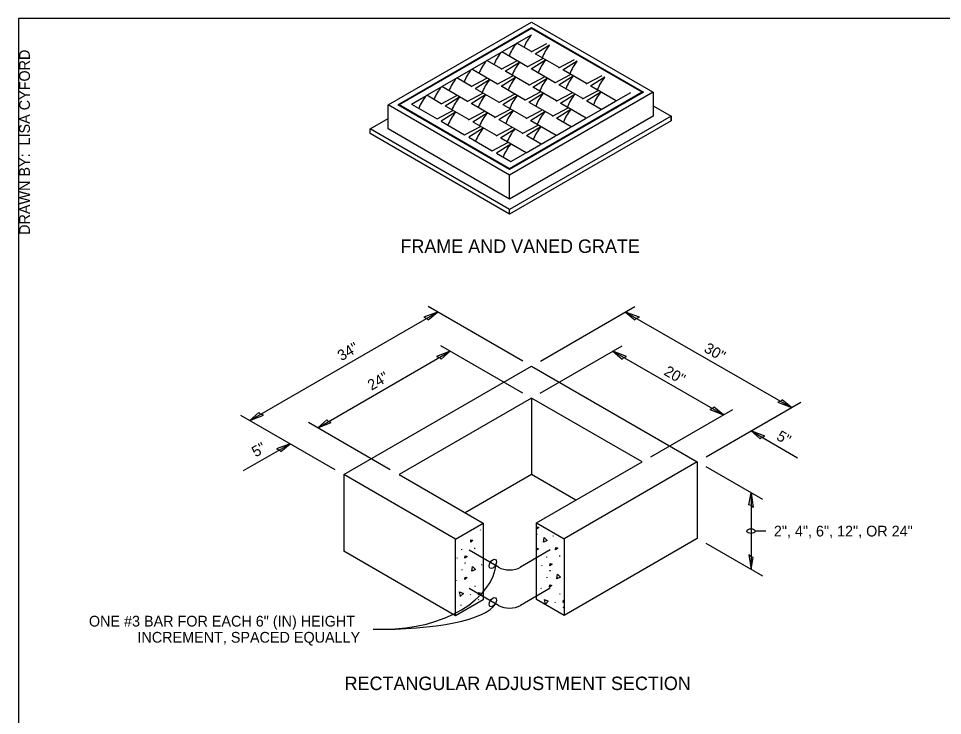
# Model space of a CAD drawing. Extents: x 99862 to 103151, y 100000 to 102076.
# Drawn here: x 99862 to 101238, y 101038 to 102076 of the extents above; entities that cross this region are included whole.
import ezdxf

# ---------------------------------------------------------------- set-up
doc = ezdxf.new("R2010")
doc.units = 0
for name, color, linetype in [('Level 1', 7, 'Continuous'), ('Level 11', 7, 'Continuous'), ('Level 12', 7, 'Continuous'), ('Level 13', 7, 'Continuous'), ('Level 15', 7, 'Continuous'), ('Level 17', 7, 'Continuous'), ('Level 20', 7, 'Continuous'), ('Level 3', 7, 'Continuous'), ('Level 44', 7, 'Continuous'), ('Level 62', 7, 'Continuous'), ('Level 8', 7, 'Continuous'), ('Level 9', 7, 'Continuous')]:
    doc.layers.add(name, color=color, linetype=linetype)

msp = doc.modelspace()

# ---------------------------------------------------------------- linework, layer by layer
at = {"layer": 'Level 1'}
msp.add_lwpolyline([(99862, 99999.5), (103151, 99999.5), (103151, 102075.5), (99862, 102075.5)], close=True, dxfattribs=at)
at = {"layer": 'Level 11'}
for p, q in [((100346.6, 101396.2), (100626.3, 101557.6)), ((100626.3, 101557.6), (100873, 101415.2)), ((100626.3, 101510.1), (100428.8, 101396.2)), ((100626.3, 101510.1), (100626.3, 101453.1)), ((100790.8, 101415.2), (100626.3, 101510.1)), ((100626.3, 101453.1), (100626.3, 101396.2)), ((100633.5, 101324.3), (100790.8, 101415.2)), ((100873, 101415.2), (100674.6, 101300.6)), ((100873, 101415.2), (100873, 101358.2)), ((100346.6, 101396.2), (100346.6, 101339.2)), ((100512.9, 101300.1), (100346.6, 101396.2)), ((100428.8, 101396.2), (100554, 101323.9)), ((100626.3, 101396.2), (100527.5, 101339.2)), ((100692.1, 101358.2), (100626.3, 101396.2)), ((100873, 101358.2), (100873, 101301.2)), ((100346.6, 101339.2), (100346.6, 101282.2)), ((100873, 101301.2), (100674.6, 101186.6)), ((100512.9, 101186.1), (100346.6, 101282.2))]:
    msp.add_line(p, q, dxfattribs=at)
at = {"layer": 'Level 12'}
for p, q in [((100626.3, 102060.7), (100428.8, 101946.7)), ((100790.8, 101965.7), (100626.3, 102060.7)), ((100604.3, 102038.6), (100626, 102051.1)), ((100582, 102025.6), (100603.7, 102038.2)), ((100625.9, 102026.1), (100604.3, 102038.6)), ((100625.5, 102025.8), (100648.9, 102038.2)), ((100653, 102035.8), (100631.7, 102022.3)), ((100559.6, 102012.7), (100581.3, 102025.3)), ((100620, 102003.7), (100582, 102025.6)), ((100667.1, 102002.3), (100632.4, 102022.4)), ((100537.2, 101999.8), (100558.9, 102012.4)), ((100581.2, 102000.3), (100559.6, 102012.7)), ((100580.8, 102000), (100604.2, 102012.3)), ((100608.3, 102010), (100586.9, 101996.5)), ((100619.6, 102003.4), (100643, 102015.8)), ((100647.1, 102013.4), (100625.7, 101999.9)), ((100666.6, 102002.1), (100690, 102014.4)), ((100694.1, 102012), (100672.8, 101998.5)), ((100514.9, 101986.9), (100536.6, 101999.4)), ((100575.3, 101977.8), (100537.2, 101999.8)), ((100622.3, 101976.5), (100587.6, 101996.5)), ((100661.2, 101979.9), (100626.4, 102000)), ((100660.7, 101979.7), (100684.1, 101992)), ((100708.2, 101978.6), (100673.5, 101998.6)), ((100492.5, 101974), (100514.2, 101986.5)), ((100536.5, 101974.4), (100514.9, 101986.9)), ((100536, 101974.2), (100559.4, 101986.5)), ((100563.5, 101984.1), (100542.2, 101970.6)), ((100574.8, 101977.6), (100598.2, 101989.9)), ((100602.4, 101987.6), (100581, 101974)), ((100621.9, 101976.3), (100645.3, 101988.6)), ((100649.4, 101986.2), (100628.1, 101972.7)), ((100688.2, 101989.6), (100666.9, 101976.1)), ((100707.7, 101978.3), (100731.1, 101990.7)), ((100735.3, 101988.3), (100713.9, 101974.8)), ((100470.1, 101961.1), (100491.8, 101973.6)), ((100530.6, 101952), (100492.5, 101974)), ((100530.1, 101951.8), (100553.5, 101964.1)), ((100577.6, 101950.7), (100542.9, 101970.7)), ((100616.4, 101954.1), (100581.7, 101974.1)), ((100790.8, 101965.7), (100593.4, 101851.7)), ((100616, 101953.9), (100639.4, 101966.2)), ((100663.5, 101952.8), (100628.8, 101972.8)), ((100663, 101952.5), (100686.4, 101964.8)), ((100702.3, 101956.2), (100667.6, 101976.2)), ((100701.8, 101955.9), (100725.2, 101968.3)), ((100729.3, 101965.9), (100708, 101952.4)), ((100752.4, 101953.1), (100714.6, 101974.9)), ((100752.4, 101953.1), (100773.8, 101965.4)), ((100790.8, 101965.7), (100790.6, 101964.4)), ((100447.3, 101947.9), (100469.5, 101960.7)), ((100491.7, 101948.6), (100470.1, 101961.1)), ((100491.3, 101948.4), (100514.7, 101960.7)), ((100518.8, 101958.3), (100497.5, 101944.8)), ((100557.6, 101961.7), (100536.3, 101948.2)), ((100577.2, 101950.4), (100600.6, 101962.8)), ((100604.7, 101960.4), (100583.3, 101946.9)), ((100643.5, 101963.8), (100622.1, 101950.3)), ((100657.6, 101930.3), (100622.8, 101950.4)), ((100690.5, 101962.5), (100669.2, 101949)), ((100730, 101940.2), (100708.7, 101952.5)), ((100730, 101940.2), (100751.4, 101952.5)), ((100593.4, 101851.7), (100428.8, 101946.7)), ((100429, 101945.4), (100428.8, 101946.7)), ((100447.3, 101947.9), (100485.4, 101926)), ((100485.4, 101926), (100508.8, 101938.3)), ((100532.9, 101924.9), (100498.2, 101944.9)), ((100532.4, 101924.6), (100555.8, 101936.9)), ((100571.7, 101928.3), (100537, 101948.3)), ((100571.2, 101928), (100594.6, 101940.4)), ((100598.8, 101938), (100577.4, 101924.5)), ((100618.7, 101926.9), (100584, 101947)), ((100618.3, 101926.7), (100641.7, 101939)), ((100645.8, 101936.6), (100624.5, 101923.1)), ((100657.1, 101930.1), (100680.5, 101942.4)), ((100684.6, 101940.1), (100663.3, 101926.6)), ((100707.7, 101927.2), (100669.9, 101949)), ((100707.7, 101927.2), (100729.1, 101939.6)), ((100512.9, 101935.9), (100491.6, 101922.4)), ((100559.9, 101934.6), (100538.6, 101921.1)), ((100612.8, 101904.5), (100578.1, 101924.6)), ((100662.9, 101901.4), (100625.2, 101923.2)), ((100685.3, 101914.3), (100664, 101926.6)), ((100685.3, 101914.3), (100706.7, 101926.7)), ((100491.6, 101922.4), (100526.5, 101902.2)), ((100526.5, 101902.2), (100549.9, 101914.5)), ((100554, 101912.2), (100532.7, 101898.6)), ((100574, 101901.1), (100539.3, 101921.1)), ((100573.6, 101900.9), (100597, 101913.2)), ((100601.1, 101910.8), (100579.7, 101897.3)), ((100612.4, 101904.3), (100635.8, 101916.6)), ((100639.9, 101914.2), (100618.5, 101900.7)), ((100662.9, 101901.4), (100684.3, 101913.8)), ((100532.7, 101898.6), (100567.6, 101878.5)), ((100618.2, 101875.6), (100580.4, 101897.4)), ((100640.6, 101888.5), (100619.3, 101900.8)), ((100640.6, 101888.5), (100662, 101900.9)), ((100567.6, 101878.5), (100591, 101890.8)), ((100595.2, 101888.4), (100573.8, 101874.9)), ((100618.2, 101875.6), (100639.6, 101888)), ((100573.8, 101874.9), (100595.4, 101862.4)), ((100595.4, 101862.4), (100617.3, 101875)), ((100593.4, 101850.6), (100593.4, 101851.7))]:
    msp.add_line(p, q, dxfattribs=at)
for centre, major_axis, ratio, start_param, end_param in [((100639.8, 102026.4), (17.8, 36.7), 0.619773, 1.161599, 1.703913), ((100617.5, 102013.5), (17.8, 36.7), 0.619773, 1.161599, 1.703913), ((100664.9, 102011.9), (17.9, 36.6), 0.569297, 1.174658, 1.709128), ((100595.1, 102000.6), (17.8, 36.7), 0.619773, 1.161599, 1.703913), ((100631.7, 102021.1), (0.64, 1.31), 0.569297, 6.243649, 7.029047), ((100572.7, 101987.6), (17.8, 36.7), 0.619773, 1.161599, 1.703913), ((100620.2, 101986.1), (17.9, 36.6), 0.569297, 1.174658, 1.709128), ((100659, 101989.5), (17.9, 36.6), 0.569297, 1.174658, 1.709128), ((100647.1, 102012.2), (0.64, 1.31), 0.569297, 0.745861, 1.174658), ((100706.1, 101988.1), (17.9, 36.6), 0.569297, 1.174658, 1.709128), ((100694.2, 102010.8), (0.64, 1.31), 0.569297, 0.745861, 1.174658), ((100550.4, 101974.7), (17.8, 36.7), 0.619773, 1.161599, 1.703913), ((100587, 101995.2), (0.64, 1.31), 0.569297, 6.243649, 7.029047), ((100625.8, 101998.7), (0.64, 1.31), 0.569297, 6.243649, 7.029047), ((100672.8, 101997.3), (0.64, 1.31), 0.569297, 6.243649, 7.029047), ((100528, 101961.8), (17.8, 36.7), 0.619773, 1.161599, 1.703913), ((100575.5, 101960.2), (17.9, 36.6), 0.569297, 1.174658, 1.709128), ((100614.3, 101963.6), (17.9, 36.6), 0.569297, 1.174658, 1.709128), ((100602.4, 101986.3), (0.64, 1.31), 0.569297, 0.745861, 1.174658), ((100661.3, 101962.3), (17.9, 36.6), 0.569297, 1.174658, 1.709128), ((100649.4, 101985), (0.64, 1.31), 0.569297, 0.745861, 1.174658), ((100700.2, 101965.7), (17.9, 36.6), 0.569297, 1.174658, 1.709128), ((100688.2, 101988.4), (0.64, 1.31), 0.569297, 0.745861, 1.174658), ((100747.2, 101964.4), (17.9, 36.6), 0.569297, 1.174658, 1.709128), ((100735.3, 101987.1), (0.64, 1.31), 0.569297, 0.745861, 1.174658), ((100505.6, 101948.9), (17.8, 36.7), 0.619773, 1.161599, 1.703913), ((100542.2, 101969.4), (0.64, 1.31), 0.569297, 6.243649, 7.029047), ((100581.1, 101972.8), (0.64, 1.31), 0.569297, 6.243649, 7.029047), ((100628.1, 101971.5), (0.64, 1.31), 0.569297, 6.243649, 7.029047), ((100666.9, 101974.9), (0.64, 1.31), 0.569297, 6.243649, 7.029047), ((100714, 101973.6), (0.64, 1.31), 0.569297, 6.243649, 7.029047), ((100741.3, 101942), (17.9, 36.6), 0.569297, 1.174658, 1.709128), ((100729.4, 101964.7), (0.64, 1.31), 0.569297, 0.745861, 1.174658), ((100483.3, 101936), (17.8, 36.7), 0.619773, 1.161599, 1.714552), ((100530.7, 101934.4), (17.9, 36.6), 0.569297, 1.174658, 1.709128), ((100569.6, 101937.8), (17.9, 36.6), 0.569297, 1.174658, 1.709128), ((100557.7, 101960.5), (0.64, 1.31), 0.569297, 0.745861, 1.174658), ((100616.6, 101936.5), (17.9, 36.6), 0.569297, 1.174658, 1.709128), ((100604.7, 101959.2), (0.64, 1.31), 0.569297, 0.745861, 1.174658), ((100622.2, 101949.1), (0.64, 1.31), 0.569297, 6.243649, 7.029047), ((100655.4, 101939.9), (17.9, 36.6), 0.569297, 1.174658, 1.709128), ((100643.5, 101962.6), (0.64, 1.31), 0.569297, 0.745861, 1.174658), ((100702.5, 101938.6), (17.9, 36.6), 0.569297, 1.174658, 1.709128), ((100690.6, 101961.3), (0.64, 1.31), 0.569297, 0.745861, 1.174658), ((100708, 101951.2), (0.64, 1.31), 0.569297, 6.243649, 7.029047), ((100497.5, 101943.6), (0.64, 1.31), 0.569297, 6.243649, 7.029047), ((100536.3, 101947), (0.64, 1.31), 0.569297, 6.243649, 7.029047), ((100583.4, 101945.7), (0.64, 1.31), 0.569297, 6.243649, 7.029047), ((100610.7, 101914.1), (17.9, 36.6), 0.569297, 1.174658, 1.709128), ((100598.8, 101936.8), (0.64, 1.31), 0.569297, 0.745861, 1.174658), ((100645.8, 101935.4), (0.64, 1.31), 0.569297, 0.745861, 1.174658), ((100669.2, 101947.8), (0.64, 1.31), 0.569297, 6.243649, 7.029047), ((100696.6, 101916.1), (17.9, 36.6), 0.569297, 1.174658, 1.709128), ((100684.6, 101938.8), (0.64, 1.31), 0.569297, 0.745861, 1.174658), ((100524.8, 101912), (17.9, 36.6), 0.569297, 1.174658, 1.719767), ((100512.9, 101934.7), (0.64, 1.31), 0.569297, 0.745861, 1.174658), ((100571.9, 101910.7), (17.9, 36.6), 0.569297, 1.174658, 1.709128), ((100560, 101933.4), (0.64, 1.31), 0.569297, 0.745861, 1.174658), ((100577.5, 101923.3), (0.64, 1.31), 0.569297, 6.243649, 7.029047), ((100624.5, 101921.9), (0.64, 1.31), 0.569297, 6.243649, 7.029047), ((100657.7, 101912.7), (17.9, 36.6), 0.569297, 1.174658, 1.709128), ((100663.3, 101925.3), (0.64, 1.31), 0.569297, 6.243649, 7.029047), ((100538.6, 101919.9), (0.64, 1.31), 0.569297, 6.243649, 7.029047), ((100566, 101888.2), (17.9, 36.6), 0.569297, 1.174658, 1.719767), ((100554.1, 101910.9), (0.64, 1.31), 0.569297, 0.745861, 1.174658), ((100613, 101886.9), (17.9, 36.6), 0.569297, 1.174658, 1.709128), ((100601.1, 101909.6), (0.64, 1.31), 0.569297, 0.745861, 1.174658), ((100651.8, 101890.3), (17.9, 36.6), 0.569297, 1.174658, 1.709128), ((100639.9, 101913), (0.64, 1.31), 0.569297, 0.745861, 1.174658), ((100579.8, 101896.1), (0.64, 1.31), 0.569297, 6.243649, 7.029047), ((100618.6, 101899.5), (0.64, 1.31), 0.569297, 6.243649, 7.029047), ((100607.1, 101864.5), (17.9, 36.6), 0.569297, 1.174658, 1.719767), ((100595.2, 101887.2), (0.64, 1.31), 0.569297, 0.745861, 1.174658)]:
    msp.add_ellipse(centre, major_axis=major_axis, ratio=ratio, start_param=start_param, end_param=end_param, dxfattribs=at)
at = {"layer": 'Level 13'}
for p, q in [((100549.5, 101313.8), (100550.2, 101313.3)), ((100633.5, 101307.7), (100633.8, 101307.5)), ((100633.6, 101307.9), (100634.3, 101307.4)), ((100658.5, 101304.5), (100658.6, 101305.7)), ((100522.3, 101284.2), (100522.4, 101285.4)), ((100541.8, 101285.9), (100541.9, 101287.1)), ((100514.7, 101272.7), (100515.2, 101271.7)), ((100526.5, 101265), (100527.3, 101264.4)), ((100527.1, 101264.9), (100527.8, 101264.3)), ((100552, 101261.4), (100552.1, 101262.6)), ((100648.7, 101272.7), (100648.8, 101273.9)), ((100668.2, 101274.4), (100668.3, 101275.6)), ((100522.8, 101253.8), (100522.9, 101255)), ((100641.1, 101261.2), (100641.6, 101260.2)), ((100652.9, 101253.5), (100653.6, 101252.9)), ((100653.5, 101253.4), (100654.2, 101252.8)), ((100513.4, 101238.9), (100514.1, 101238.3)), ((100649.2, 101242.3), (100649.2, 101243.5)), ((100542.2, 101229.6), (100542.3, 101230.8)), ((100639.8, 101227.4), (100640.5, 101226.8)), ((100534.6, 101218.1), (100535.1, 101217.1)), ((100546.4, 101210.4), (100547.1, 101209.9)), ((100547, 101210.3), (100547.7, 101209.8)), ((100668.5, 101218.1), (100668.6, 101219.3)), ((100521.3, 101201.2), (100521.4, 101202.5)), ((100660.9, 101206.6), (100661.4, 101205.6)), ((100672.8, 101198.9), (100673.5, 101198.4)), ((100673.3, 101198.8), (100674.1, 101198.3))]:
    msp.add_line(p, q, dxfattribs=at)
for points in [[(100633.5, 101315.1), (100633.9, 101318.5), (100636.8, 101317.6), (100633.5, 101315.1)], [(100535.6, 101295.8), (100535.9, 101299.3), (100538.9, 101298.4), (100535.6, 101295.8)], [(100643.9, 101295.6), (100644.9, 101302.7), (100649.4, 101298.1), (100644, 101295.6)], [(100633.5, 101285.4), (100633.6, 101286.8), (100636.6, 101285.9), (100633.5, 101283.5)], [(100661.9, 101284.3), (100662.3, 101287.8), (100665.2, 101286.9), (100661.9, 101284.3)], [(100527, 101272), (100527.3, 101275.4), (100530.3, 101274.5), (100527, 101272)], [(100653.4, 101260.5), (100653.7, 101263.9), (100656.7, 101263), (100653.4, 101260.5)], [(100537.4, 101252.5), (100538.4, 101259.6), (100542.9, 101255), (100537.5, 101252.5)], [(100526.8, 101240.3), (100527.1, 101243.7), (100530.1, 101242.8), (100526.8, 101240.3)], [(100663.8, 101241), (100664.8, 101248.1), (100669.2, 101243.5), (100663.9, 101241)], [(100520.4, 101214.9), (100518.9, 101221.9), (100524.6, 101219.1), (100520.5, 101215)], [(100546.9, 101217.4), (100547.2, 101220.9), (100550.2, 101220), (100546.9, 101217.4)], [(100653.1, 101228.8), (100653.5, 101232.2), (100656.5, 101231.3), (100653.1, 101228.8)], [(100646.7, 101203.4), (100645.2, 101210.4), (100651, 101207.6), (100646.8, 101203.5)], [(100673.2, 101205.9), (100673.6, 101209.4), (100674.6, 101209.1)], [(100674.6, 101207), (100673.2, 101205.9)]]:
    msp.add_lwpolyline(points, dxfattribs=at)
at = {"layer": 'Level 15'}
for p, q in [((100206.4, 101476.9), (100486.1, 101638.4)), ((100613.3, 101565.1), (100472.2, 101646.4)), ((100639.3, 101565.1), (100780.2, 101646.4)), ((100766.3, 101638.4), (101013.1, 101496)), ((100307.6, 101466), (100505, 101580)), ((100613.3, 101517.6), (100491.1, 101588)), ((100639.2, 101517.6), (100761.2, 101588.1)), ((100747.3, 101580.1), (100911.8, 101485.1)), ((100886, 101422.7), (101027, 101503.9)), ((100333.6, 101403.6), (100193.1, 101484.5)), ((100803.8, 101422.7), (100925.7, 101493.1)), ((100415.8, 101403.6), (100293.7, 101474)), ((100953.1, 101461.3), (101022.4, 101421.3)), ((100197.2, 101402.3), (100266.5, 101442.3)), ((100970.4, 101359.1), (100886, 101407.7)), ((100953, 101369.1), (100953, 101255.1)), ((100975, 101312.1), (100959, 101312.1)), ((100970.4, 101245.1), (100886, 101293.7)), ((100390.2, 101166), (100406.2, 101166))]:
    msp.add_line(p, q, dxfattribs=at)
for centre, major_axis in [((100953, 101312.1), (-6, 0)), ((100568.5, 101263.3), (3.75, 6.5)), ((100568.5, 101206.3), (3.75, 6.5))]:
    msp.add_ellipse(centre, major_axis=major_axis, ratio=0.57735, dxfattribs=at)
for centre, major_axis, ratio, end_param in [((100406.2, 101270.7), (167.8, 0), 0.623729, 6.233084), ((100406.2, 101209.8), (167.7, 0), 0.260817, 6.242098)]:
    msp.add_ellipse(centre, major_axis=major_axis, ratio=ratio, start_param=4.71238, end_param=end_param, dxfattribs=at)
at = {"layer": 'Level 17'}
for points in [[(100576.9, 101258.4), (100533.4, 101283.5)], [(100654.1, 101284), (100609.8, 101258.4)], [(100576.9, 101201.4), (100533.4, 101226.5)], [(100654.1, 101227), (100609.8, 101201.4)]]:
    msp.add_lwpolyline(points, dxfattribs=at)
for centre in [(100593.4, 101267.9), (100593.4, 101210.9)]:
    msp.add_ellipse(centre, major_axis=(-23.3, 0), ratio=0.57735, start_param=0.785398, end_param=2.356194, dxfattribs=at)
at = {"layer": 'Level 3'}
for p, q in [((100412.4, 101946.7), (100626.3, 102070.2)), ((100426.8, 101946.7), (100626.3, 102061.9)), ((100626.3, 102070.2), (100807.2, 101965.7)), ((100626.3, 102060.7), (100626.3, 102061.9)), ((100626.3, 102061.9), (100792.8, 101965.7)), ((100807.2, 101965.7), (100593.3, 101842.2)), ((100792.8, 101965.7), (100593.3, 101850.6)), ((100807.2, 101965.7), (100807.2, 101930.1)), ((100412.4, 101911.1), (100412.4, 101946.7)), ((100593.3, 101842.2), (100412.4, 101946.7)), ((100593.3, 101850.6), (100426.8, 101946.7)), ((100807.2, 101945.5), (100834, 101930.1)), ((100385.6, 101911.1), (100412.4, 101926.6)), ((100834, 101930.1), (100593.3, 101791.2)), ((100807.2, 101930.1), (100593.3, 101806.6)), ((100834, 101923), (100593.3, 101784.1)), ((100834, 101923), (100834, 101930.1)), ((100385.6, 101904), (100385.6, 101911.1)), ((100593.3, 101791.2), (100385.6, 101911.1)), ((100593.3, 101806.6), (100412.4, 101911.1)), ((100593.3, 101784.1), (100385.6, 101904)), ((100593.3, 101806.6), (100593.3, 101842.2)), ((100593.3, 101784.1), (100593.3, 101791.2))]:
    msp.add_line(p, q, dxfattribs=at)
at = {"layer": 'Level 44'}
for points in [[(100512.9, 101300.1), (100554, 101323.9), (100554, 101209.9), (100512.9, 101186.1)], [(100633.5, 101324.3), (100674.6, 101300.6), (100674.6, 101186.6), (100633.5, 101210.4)]]:
    msp.add_lwpolyline(points, close=True, dxfattribs=at)
at = {"layer": 'Level 8'}
for points in [[(100486.1, 101638.4), (100465.7, 101630.5), (100469.9, 101629), (100472.4, 101626.6)], [(100766.3, 101638.4), (100780, 101626.7), (100782.6, 101629.1), (100786.7, 101630.5)], [(100505, 101580), (100484.6, 101572.1), (100488.8, 101570.6), (100491.3, 101568.2)], [(100747.3, 101580.1), (100761, 101568.4), (100763.6, 101570.7), (100767.7, 101572.2)], [(100911.8, 101485.1), (100898.2, 101496.9), (100895.6, 101494.5), (100891.5, 101493)], [(101013.1, 101496), (100999.4, 101507.7), (100996.9, 101505.3), (100992.7, 101503.9)], [(100206.4, 101476.9), (100226.8, 101484.8), (100222.6, 101486.3), (100220.1, 101488.7)], [(100307.6, 101466), (100327.9, 101473.9), (100323.8, 101475.4), (100321.2, 101477.8)], [(100953.1, 101461.3), (100966.8, 101449.6), (100969.3, 101452), (100973.4, 101453.4)], [(100266.5, 101442.3), (100246.1, 101434.4), (100250.2, 101432.9), (100252.8, 101430.5)], [(100953, 101369.1), (100956.4, 101347.5), (100953, 101350.3), (100949.7, 101351.3)], [(100953, 101255.1), (100956.4, 101272.8), (100953, 101273.8), (100949.7, 101276.7)]]:
    msp.add_lwpolyline(points, close=True, dxfattribs=at)
at = {"layer": 'Level 9'}
msp.add_lwpolyline([(100412.4, 101926.6), (100412.4, 101946.7), (100626.3, 102070.2), (100807.2, 101965.7), (100807.2, 101945.5), (100834, 101930.1), (100834, 101923), (100593.3, 101784.1), (100385.6, 101904), (100385.6, 101911.1), (100412.4, 101926.6)], dxfattribs=at)

# ---------------------------------------------------------------- texts
at = {"layer": 'Level 20'}
for s, height, p in [('FRAME AND VANED GRATE', 20, (100430.8, 101726.4)), ('ONE #3 BAR FOR EACH 6" (IN) HEIGHT', 16, (99966.9, 101170)), ('INCREMENT, SPACED EQUALLY', 16, (100039.2, 101146)), ('RECTANGULAR ADJUSTMENT SECTION', 20, (100347.7, 101075.4))]:
    msp.add_text(s, height=height, dxfattribs=at).set_placement(p)
for s, rotation, p in [('34"', 29.9987, (100342.9, 101564.9)), ('30"', 330.0271, (100881.7, 101579.9)), ('20"', 330.0271, (100822, 101545.6)), ('24"', 29.9987, (100387.7, 101521)), ('5"', 330.0271, (100989.6, 101449.1)), ('5"', 29.9987, (100215.3, 101421.7)), ('2", 4", 6", 12", OR 24"', 360, (100987, 101304.1))]:
    msp.add_text(s, height=16, rotation=rotation, dxfattribs=at).set_placement(p)
at = {"layer": 'Level 62'}
msp.add_text('DRAWN BY:  LISA CYFORD', height=16, rotation=90, dxfattribs=at).set_placement((99879, 101753.3))

doc.saveas('drawing.dxf')
